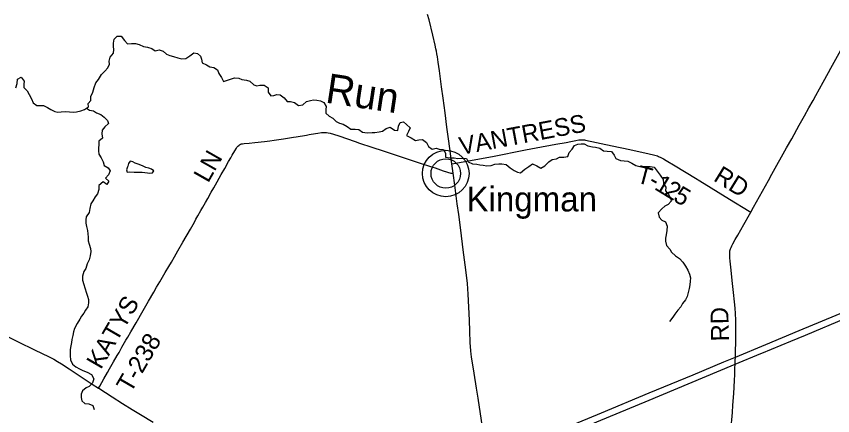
# Model space of a CAD drawing. Extents: x 1442749 to 1756758, y 235267 to 677782.
# Drawn here: x 1554943 to 1568709, y 545783 to 552520 of the extents above; entities that cross this region are included whole.
import ezdxf

# ---------------------------------------------------------------- set-up
doc = ezdxf.new("R2010")
doc.units = 0
for name, color, linetype in [('GM_X_Interstate_Route', 7, 'Continuous'), ('GM_X_Minor_Lake', 7, 'Continuous'), ('GM_X_Minor_River', 7, 'Continuous'), ('GM_X_Minor_River_Text', 7, 'Continuous'), ('GM_X_State_Route', 7, 'Continuous'), ('GM_X_Township_Road', 7, 'Continuous'), ('GM_X_Township_Road_Text', 7, 'Continuous'), ('GM_X_Unincorporated', 7, 'Continuous'), ('GM_X_Unincorporated_Location', 7, 'Continuous'), ('GM_X_Unincorporated_Text', 7, 'Continuous')]:
    doc.layers.add(name, color=color, linetype=linetype)

msp = doc.modelspace()

# ---------------------------------------------------------------- linework, layer by layer
at = {"layer": 'GM_X_Interstate_Route'}
for points in [[(1563860, 545437), (1564812, 545832), (1565614, 546167), (1566357, 546474), (1566874, 546691), (1567069, 546771), (1567581, 546983), (1568144, 547217), (1569716, 547872)], [(1568003, 547040), (1568252, 547142), (1568944, 547433)], [(1567515, 546839), (1568003, 547040)], [(1562882, 544919), (1562894, 544924), (1563250, 545070), (1563323, 545097), (1563958, 545359), (1564314, 545504), (1564801, 545709), (1565546, 546018), (1567065, 546652), (1567496, 546832), (1567515, 546839)]]:
    msp.add_lwpolyline(points, dxfattribs=at)
at = {"layer": 'GM_X_Minor_Lake'}
for points in [[(1556815, 549979), (1556798, 549931), (1556814, 549891), (1556854, 549894), (1556930, 549893), (1556974, 549888), (1557066, 549890), (1557110, 549885), (1557156, 549882), (1557196, 549871), (1557242, 549878), (1557253, 549895)], [(1557253, 549895), (1557263, 549912), (1557222, 549941), (1557176, 549958), (1557128, 549971), (1557084, 549992), (1557043, 550011), (1556997, 550028), (1556949, 550043), (1556909, 550063), (1556865, 550076), (1556837, 550035), (1556822, 549993), (1556815, 549979)]]:
    msp.add_lwpolyline(points, dxfattribs=at)
at = {"layer": 'GM_X_Minor_River'}
for points in [[(1556581, 551896), (1556588, 551960), (1556581, 552013), (1556584, 552067), (1556592, 552135), (1556643, 552186), (1556709, 552185), (1556766, 552113), (1556817, 552058), (1556885, 552061), (1556951, 552062), (1557017, 552044), (1557088, 552013), (1557156, 551997), (1557226, 551978), (1557285, 551935), (1557354, 551955), (1557418, 551932), (1557477, 551883), (1557534, 551857), (1557594, 551844), (1557668, 551817), (1557736, 551803), (1557802, 551810), (1557867, 551853), (1557934, 551902), (1557998, 551894), (1558049, 551849), (1558064, 551797), (1558079, 551734), (1558151, 551699), (1558206, 551670), (1558272, 551658), (1558336, 551619), (1558358, 551554), (1558403, 551485), (1558434, 551422), (1558488, 551437), (1558553, 551460), (1558621, 551481), (1558696, 551477), (1558747, 551454), (1558823, 551445), (1558883, 551424), (1558948, 551364), (1559000, 551347), (1559052, 551356), (1559120, 551357), (1559188, 551313), (1559188, 551239), (1559233, 551180), (1559283, 551183), (1559336, 551198), (1559392, 551195), (1559457, 551143), (1559512, 551082), (1559564, 551081), (1559636, 551068), (1559701, 551018), (1559775, 551027), (1559834, 551080), (1559903, 551101), (1559957, 551109), (1560013, 551106), (1560075, 551095), (1560127, 551068), (1560170, 550997), (1560161, 550945), (1560161, 550887), (1560219, 550838), (1560280, 550800), (1560339, 550745), (1560391, 550716), (1560456, 550701), (1560520, 550663), (1560583, 550618), (1560657, 550614), (1560719, 550611), (1560779, 550568), (1560861, 550556), (1560941, 550557), (1560991, 550560), (1561063, 550570), (1561118, 550585), (1561181, 550630), (1561249, 550649), (1561319, 550599), (1561379, 550596), (1561386, 550664), (1561413, 550730), (1561470, 550740), (1561525, 550693), (1561586, 550638), (1561559, 550576), (1561523, 550511), (1561599, 550469), (1561672, 550424), (1561728, 550435), (1561793, 550441), (1561860, 550390), (1561892, 550325)], [(1554932, 551316), (1554955, 551387), (1554962, 551459), (1555023, 551492), (1555074, 551423), (1555071, 551373), (1555068, 551319), (1555125, 551264), (1555160, 551199), (1555200, 551128), (1555229, 551059), (1555290, 551016), (1555346, 551013), (1555401, 551016), (1555466, 550984), (1555522, 550949), (1555591, 550912), (1555645, 550903), (1555699, 550908), (1555766, 550914), (1555838, 550907), (1555904, 550903), (1555960, 550908), (1556030, 550927), (1556095, 550948), (1556158, 550995), (1556155, 551047), (1556200, 551100), (1556200, 551168), (1556231, 551240), (1556253, 551320), (1556282, 551397), (1556328, 551456), (1556379, 551538), (1556437, 551597), (1556488, 551652), (1556513, 551711), (1556506, 551764), (1556528, 551831), (1556581, 551896)], [(1556126, 550971), (1556177, 550936), (1556243, 550927), (1556296, 550892), (1556366, 550862), (1556425, 550817), (1556482, 550760), (1556495, 550709), (1556434, 550654), (1556391, 550601), (1556385, 550535), (1556396, 550465), (1556337, 550416), (1556332, 550352), (1556331, 550299), (1556328, 550249), (1556337, 550197), (1556375, 550132), (1556408, 550067), (1556423, 550005), (1556490, 549963), (1556527, 549913), (1556498, 549845), (1556445, 549790), (1556504, 549739), (1556467, 549681), (1556407, 549727), (1556335, 549666)], [(1561892, 550325), (1561956, 550280), (1562022, 550296), (1562076, 550279), (1562144, 550272), (1562181, 550209), (1562180, 550143), (1562254, 550135), (1562324, 550134), (1562390, 550119), (1562468, 550129), (1562534, 550122), (1562563, 550065), (1562634, 550031), (1562711, 550026), (1562762, 550013), (1562813, 550010), (1562880, 549996), (1562951, 550003), (1563015, 550024), (1563082, 550029), (1563132, 550032), (1563204, 550022), (1563271, 549965), (1563336, 549917), (1563392, 549890), (1563443, 549877), (1563517, 549942), (1563588, 549986), (1563649, 550029), (1563720, 549996), (1563788, 549956), (1563855, 549999), (1563922, 550066), (1563981, 550107), (1564050, 550117), (1564100, 550144), (1564177, 550143), (1564245, 550156), (1564266, 550221), (1564314, 550277), (1564357, 550340), (1564411, 550361), (1564466, 550370), (1564516, 550371), (1564583, 550333), (1564657, 550316), (1564711, 550313), (1564785, 550293), (1564842, 550248), (1564908, 550243), (1564980, 550239), (1565025, 550176), (1565052, 550121), (1565132, 550086), (1565192, 550083), (1565254, 550075), (1565321, 550040), (1565391, 550002), (1565459, 549985), (1565509, 549986), (1565577, 549987), (1565629, 549988), (1565697, 549974), (1565752, 549909), (1565798, 549838), (1565853, 549767), (1565856, 549698), (1565897, 549637), (1565893, 549573), (1565941, 549512)], [(1556335, 549666), (1556336, 549596), (1556314, 549524), (1556275, 549473), (1556234, 549408), (1556201, 549356), (1556185, 549278), (1556172, 549209), (1556118, 549138), (1556115, 549084), (1556116, 549033), (1556127, 548975), (1556142, 548909), (1556147, 548851), (1556152, 548796), (1556156, 548732), (1556173, 548678), (1556196, 548603), (1556197, 548553), (1556187, 548481), (1556172, 548411), (1556140, 548346), (1556113, 548264), (1556084, 548213), (1556056, 548139), (1556061, 548067), (1556079, 547993), (1556098, 547940), (1556126, 547849), (1556141, 547799), (1556158, 547741), (1556161, 547687), (1556147, 547617), (1556112, 547565), (1556081, 547514), (1556044, 547462), (1556013, 547411), (1555968, 547338), (1555924, 547253), (1555909, 547199), (1555897, 547137), (1555878, 547069), (1555875, 547019), (1555862, 546961), (1555851, 546899), (1555851, 546845), (1555850, 546795), (1555855, 546725), (1555891, 546652), (1555945, 546605), (1556006, 546574), (1556063, 546547), (1556137, 546519), (1556208, 546480), (1556248, 546405), (1556229, 546335), (1556170, 546274), (1556119, 546251), (1556056, 546202), (1556037, 546143), (1556036, 546091), (1556045, 546036), (1556096, 545987), (1556168, 545980), (1556233, 545954), (1556256, 545888)], [(1565941, 549512), (1565977, 549451), (1565984, 549399), (1565933, 549346), (1565879, 549315), (1565826, 549274), (1565768, 549203), (1565781, 549132), (1565828, 549079), (1565891, 549050), (1565916, 548981), (1565910, 548905), (1565901, 548831), (1565892, 548779), (1565888, 548725), (1565909, 548653), (1565964, 548592), (1565993, 548541), (1566061, 548478), (1566127, 548432), (1566181, 548373), (1566226, 548304), (1566269, 548239), (1566295, 548171), (1566310, 548108), (1566309, 548054), (1566303, 547988), (1566290, 547926), (1566273, 547863), (1566257, 547791), (1566226, 547739), (1566175, 547676), (1566150, 547621), (1566097, 547562), (1566047, 547498), (1566014, 547443), (1565959, 547372)]]:
    msp.add_lwpolyline(points, dxfattribs=at)
at = {"layer": 'GM_X_State_Route'}
for points in [[(1562730, 546079), (1562704, 546245), (1562665, 546498), (1562619, 546774), (1562613, 546822), (1562607, 546875), (1562598, 547016), (1562591, 547209), (1562585, 547396), (1562564, 547832), (1562551, 548015), (1562525, 548243), (1562480, 548581), (1562438, 548910), (1562403, 549176), (1562378, 549358), (1562335, 549673), (1562308, 549871), (1562297, 549950), (1562287, 550030), (1562275, 550115), (1562253, 550288), (1562230, 550453), (1562204, 550652), (1562174, 550892), (1562141, 551139), (1562114, 551328), (1562079, 551598), (1562057, 551745), (1562044, 551838), (1562036, 551886), (1562028, 551932), (1562020, 551973), (1562008, 552031), (1561968, 552203), (1561903, 552461), (1561878, 552549)], [(1554792, 547116), (1554972, 547029), (1555250, 546895), (1555495, 546776), (1555577, 546735), (1555640, 546699), (1555707, 546657), (1555836, 546573), (1555921, 546517), (1556119, 546383), (1556221, 546317), (1556331, 546247), (1556335, 546245), (1556559, 546102), (1556733, 545991), (1556897, 545889), (1557037, 545803), (1557251, 545675)], [(1563010, 543903), (1563017, 543933), (1563019, 543942), (1563020, 543949), (1563020, 543956), (1563020, 543961), (1563019, 543973), (1563014, 544009), (1562992, 544176), (1562957, 544436), (1562906, 544830), (1562898, 544897), (1562894, 544924), (1562880, 545032), (1562861, 545175), (1562833, 545406), (1562773, 545815), (1562730, 546079)]]:
    msp.add_lwpolyline(points, dxfattribs=at)
at = {"layer": 'GM_X_Township_Road'}
for points in [[(1567329, 549216), (1567376, 549299), (1567426, 549388), (1567625, 549750), (1567684, 549859), (1567933, 550303), (1568018, 550454), (1568145, 550684), (1568233, 550841), (1568308, 550976), (1568378, 551098), (1568424, 551182), (1568551, 551411), (1568637, 551570), (1568680, 551647), (1568791, 551848), (1568905, 552051), (1568995, 552212), (1569108, 552415), (1569134, 552457)], [(1556331, 546247), (1556352, 546283), (1556420, 546403), (1556480, 546512), (1556515, 546575), (1556583, 546692), (1556646, 546799), (1556675, 546850), (1556723, 546936), (1556792, 547056), (1556821, 547107), (1556875, 547197), (1556962, 547348), (1557081, 547555), (1557129, 547637), (1557174, 547714), (1557260, 547865), (1557309, 547950), (1557365, 548043), (1557454, 548196), (1557514, 548301), (1557557, 548375), (1557608, 548463), (1557667, 548566), (1557751, 548710), (1557878, 548929), (1557946, 549049), (1557971, 549095), (1558004, 549155), (1558054, 549243), (1558088, 549303), (1558132, 549380), (1558170, 549449), (1558230, 549555), (1558274, 549628), (1558328, 549725), (1558398, 549851), (1558457, 549954), (1558520, 550068), (1558558, 550133), (1558582, 550176), (1558625, 550250), (1558653, 550295), (1558668, 550317), (1558680, 550329), (1558695, 550343), (1558709, 550353), (1558725, 550361), (1558740, 550366), (1558757, 550369), (1558786, 550373), (1558868, 550381), (1558966, 550392), (1559128, 550410), (1559216, 550419), (1559293, 550430), (1559451, 550454), (1559615, 550480), (1559660, 550488), (1559834, 550517), (1559882, 550525), (1559915, 550530), (1559953, 550537), (1559989, 550543), (1560028, 550550), (1560089, 550559), (1560109, 550561), (1560125, 550562), (1560151, 550561), (1560171, 550560), (1560200, 550556), (1560235, 550547), (1560290, 550530), (1560384, 550502), (1560658, 550407), (1560730, 550382), (1560783, 550365), (1560885, 550331), (1560954, 550309), (1561112, 550255), (1561246, 550212), (1561617, 550089), (1561751, 550044), (1561926, 549988), (1562007, 549961), (1562143, 549915), (1562271, 549876), (1562283, 549874), (1562308, 549871)], [(1562287, 550030), (1562320, 550036), (1562971, 550157), (1563532, 550268), (1563712, 550303), (1564042, 550362), (1564216, 550392), (1564294, 550406), (1564380, 550424), (1564430, 550434), (1564450, 550436), (1564467, 550438), (1564482, 550438), (1564494, 550438), (1564506, 550436), (1564525, 550434), (1564543, 550430), (1564990, 550334), (1565288, 550272), (1565616, 550201), (1565688, 550185), (1565713, 550179), (1565733, 550173), (1565754, 550165), (1565774, 550156), (1565814, 550136), (1565857, 550113), (1565900, 550089), (1566052, 549997), (1566397, 549789), (1566472, 549743), (1566970, 549437), (1567303, 549232), (1567329, 549216)], [(1566992, 545535), (1567019, 545835), (1567028, 545960), (1567041, 546159), (1567054, 546375), (1567058, 546477), (1567062, 546582), (1567065, 546652), (1567067, 546713), (1567069, 546771), (1567072, 546877), (1567077, 547018), (1567079, 547136), (1567078, 547267), (1567076, 547392), (1567071, 547506), (1567066, 547598), (1567056, 547706), (1567037, 547863), (1567015, 548065), (1566998, 548238), (1566981, 548388), (1566975, 548443), (1566973, 548495), (1566973, 548534), (1566977, 548566), (1566985, 548595), (1566995, 548622), (1567007, 548649), (1567026, 548683), (1567067, 548757), (1567109, 548828), (1567214, 549010), (1567308, 549179), (1567329, 549216)]]:
    msp.add_lwpolyline(points, dxfattribs=at)
at = {"layer": 'GM_X_Unincorporated'}
for radius in [393, 249]:
    msp.add_circle((1562185, 549868), radius, dxfattribs=at)
at = {"layer": 'GM_X_Unincorporated_Location'}
msp.add_line((1562185, 549868), (1562185, 549868), dxfattribs=at)

# ---------------------------------------------------------------- texts
at = {"layer": 'GM_X_Minor_River_Text'}
msp.add_text('Run', height=500, rotation=351.4693, dxfattribs=at).set_placement((1560140, 551066))
at = {"layer": 'GM_X_Township_Road_Text'}
for s, rotation, p in [('VANTRESS', 10.643, (1562442, 550180)), ('LN', 60.4462, (1558177, 549696)), ('T', 345.1072, (1565383, 549720)), ('RD', 328.3585, (1566683, 549756)), ('-', 330.7005, (1565581, 549670)), ('1', 328.9059, (1565686, 549611)), ('2', 328.7136, (1565844, 549515)), ('5', 328.87, (1566003, 549419)), ('KATYS', 59.9767, (1556368, 546550)), ('RD', 91.348, (1566961, 547040)), ('T-238', 59.9238, (1556873, 546151))]:
    msp.add_text(s, height=300, rotation=rotation, dxfattribs=at).set_placement(p)
at = {"layer": 'GM_X_Unincorporated_Text'}
msp.add_text('Kingman', height=417, rotation=0, dxfattribs=at).set_placement((1562534, 549228))

doc.saveas('drawing.dxf')
